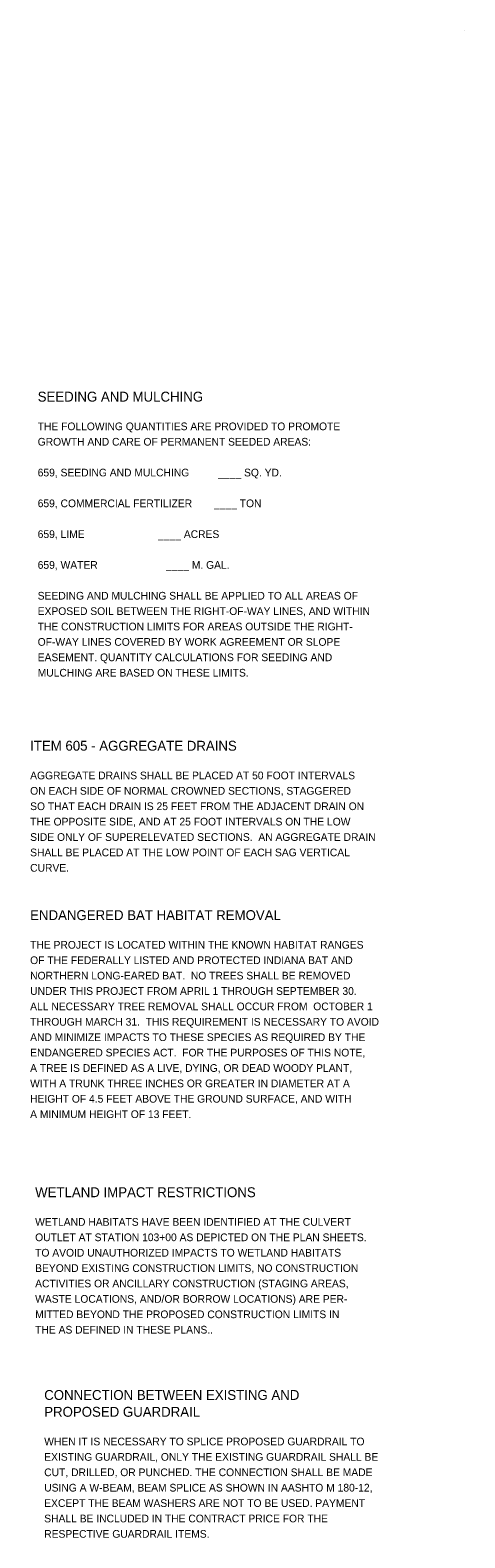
# Model space of a CAD drawing. Extents: x -30 to 80, y -20 to 49.
# Drawn here: x -8.19 to -0.28, y -0.02 to 27.4 of the extents above; entities that cross this region are included whole.
import ezdxf

# ---------------------------------------------------------------- set-up
doc = ezdxf.new("R2010")
doc.units = 0
doc.layers.add('SH_Data', color=7, linetype='Continuous')
doc.layers.add('SH_Text', color=7, linetype='Continuous')

msp = doc.modelspace()

# ---------------------------------------------------------------- linework, layer by layer
at = {"layer": 'SH_Data'}
msp.add_line((-0.279, 27.4), (-0.279, 27.4), dxfattribs=at)

# ---------------------------------------------------------------- texts
at = {"layer": 'SH_Text'}
for s, height, p in [('SEEDING AND MULCHING', 0.18, (-8.049, 20.645)), ('THE FOLLOWING QUANTITIES ARE PROVIDED TO PROMOTE', 0.14, (-8.049, 20.125)), ('GROWTH AND CARE OF PERMANENT SEEDED AREAS:', 0.14, (-8.049, 19.845)), ('659, SEEDING AND MULCHING        ', 0.14, (-8.049, 19.285)), ('  ____ SQ. YD.', 0.14, (-4.868, 19.285)), ('659, COMMERCIAL FERTILIZER       ', 0.14, (-8.049, 18.725)), ('  ____ TON', 0.14, (-4.946, 18.725)), ('659, LIME                          ', 0.14, (-8.049, 18.165)), ('____ ACRES', 0.14, (-5.859, 18.165)), ('659, WATER                         ', 0.14, (-8.049, 17.605)), ('____ M. GAL.', 0.14, (-5.714, 17.605)), ('SEEDING AND MULCHING SHALL BE APPLIED TO ALL AREAS OF', 0.14, (-8.049, 17.045)), ('EXPOSED SOIL BETWEEN THE RIGHT-OF-WAY LINES, AND WITHIN', 0.14, (-8.049, 16.765)), ('THE CONSTRUCTION LIMITS FOR AREAS OUTSIDE THE RIGHT-', 0.14, (-8.049, 16.485)), ('OF-WAY LINES COVERED BY WORK AGREEMENT OR SLOPE', 0.14, (-8.049, 16.205)), ('EASEMENT. QUANTITY CALCULATIONS FOR SEEDING AND', 0.14, (-8.049, 15.925)), ('MULCHING ARE BASED ON THESE LIMITS.', 0.14, (-8.049, 15.645)), ('ITEM 605 - AGGREGATE DRAINS', 0.18, (-8.186, 14.297)), ('AGGREGATE DRAINS SHALL BE PLACED AT 50 FOOT INTERVALS', 0.14, (-8.186, 13.777)), ('ON EACH SIDE OF NORMAL CROWNED SECTIONS, STAGGERED', 0.14, (-8.186, 13.497)), ('SO THAT EACH DRAIN IS 25 FEET FROM THE ADJACENT DRAIN ON', 0.14, (-8.186, 13.217)), ('THE OPPOSITE SIDE, AND AT 25 FOOT INTERVALS ON THE LOW', 0.14, (-8.186, 12.937)), ('SIDE ONLY OF SUPERELEVATED SECTIONS.  AN AGGREGATE DRAIN', 0.14, (-8.186, 12.657)), ('SHALL BE PLACED AT THE LOW POINT OF EACH SAG VERTICAL', 0.14, (-8.186, 12.377)), ('CURVE.', 0.14, (-8.186, 12.097)), ('ENDANGERED BAT HABITAT REMOVAL', 0.18, (-8.186, 11.217)), ('THE PROJECT IS LOCATED WITHIN THE KNOWN HABITAT RANGES', 0.14, (-8.186, 10.697)), ('OF THE FEDERALLY LISTED AND PROTECTED INDIANA BAT AND', 0.14, (-8.186, 10.417)), ('NORTHERN LONG-EARED BAT.  NO TREES SHALL BE REMOVED', 0.14, (-8.186, 10.137)), ('UNDER THIS PROJECT FROM APRIL 1 THROUGH SEPTEMBER 30.', 0.14, (-8.186, 9.857)), ('ALL NECESSARY TREE REMOVAL SHALL OCCUR FROM  OCTOBER 1', 0.14, (-8.186, 9.577)), ('THROUGH MARCH 31.  THIS REQUIREMENT IS NECESSARY TO AVOID', 0.14, (-8.186, 9.297)), ('AND MINIMIZE IMPACTS TO THESE SPECIES AS REQUIRED BY THE', 0.14, (-8.186, 9.017)), ('ENDANGERED SPECIES ACT.  FOR THE PURPOSES OF THIS NOTE,', 0.14, (-8.186, 8.737)), ('A TREE IS DEFINED AS A LIVE, DYING, OR DEAD WOODY PLANT,', 0.14, (-8.186, 8.457)), ('WITH A TRUNK THREE INCHES OR GREATER IN DIAMETER AT A', 0.14, (-8.186, 8.177)), ('HEIGHT OF 4.5 FEET ABOVE THE GROUND SURFACE, AND WITH', 0.14, (-8.186, 7.897)), ('A MINIMUM HEIGHT OF 13 FEET.', 0.14, (-8.186, 7.617)), ('WETLAND IMPACT RESTRICTIONS', 0.18, (-8.095, 6.178)), ('WETLAND HABITATS HAVE BEEN IDENTIFIED AT THE CULVERT', 0.14, (-8.095, 5.658)), ('OUTLET AT STATION 103+00 AS DEPICTED ON THE PLAN SHEETS.\xa0', 0.14, (-8.095, 5.378)), ('TO AVOID UNAUTHORIZED IMPACTS TO WETLAND HABITATS', 0.14, (-8.095, 5.098)), ('BEYOND EXISTING CONSTRUCTION LIMITS, NO CONSTRUCTION', 0.14, (-8.095, 4.818)), ('ACTIVITIES OR ANCILLARY CONSTRUCTION (STAGING AREAS,', 0.14, (-8.095, 4.538)), ('WASTE LOCATIONS, AND/OR BORROW LOCATIONS) ARE PER-', 0.14, (-8.095, 4.258)), ('MITTED BEYOND THE PROPOSED CONSTRUCTION LIMITS IN', 0.14, (-8.095, 3.978)), ('THE AS DEFINED IN THESE PLANS..\xa0\xa0\xa0 ', 0.14, (-8.095, 3.698)), ('CONNECTION BETWEEN EXISTING AND', 0.18, (-7.93, 2.491)), ('PROPOSED GUARDRAIL', 0.18, (-7.93, 2.185)), ('WHEN IT IS NECESSARY TO SPLICE PROPOSED GUARDRAIL TO', 0.14, (-7.93, 1.665)), ('EXISTING GUARDRAIL, ONLY THE EXISTING GUARDRAIL SHALL BE', 0.14, (-7.93, 1.385)), ('CUT, DRILLED, OR PUNCHED. THE CONNECTION SHALL BE MADE', 0.14, (-7.93, 1.105)), ('USING A W-BEAM, BEAM SPLICE AS SHOWN IN AASHTO M 180-12,', 0.14, (-7.93, 0.825)), ('EXCEPT THE BEAM WASHERS ARE NOT TO BE USED. PAYMENT', 0.14, (-7.93, 0.545)), ('SHALL BE INCLUDED IN THE CONTRACT PRICE FOR THE', 0.14, (-7.93, 0.265)), ('RESPECTIVE GUARDRAIL ITEMS.', 0.14, (-7.93, -0.015))]:
    msp.add_text(s, height=height, dxfattribs=at).set_placement(p)

doc.saveas('drawing.dxf')
